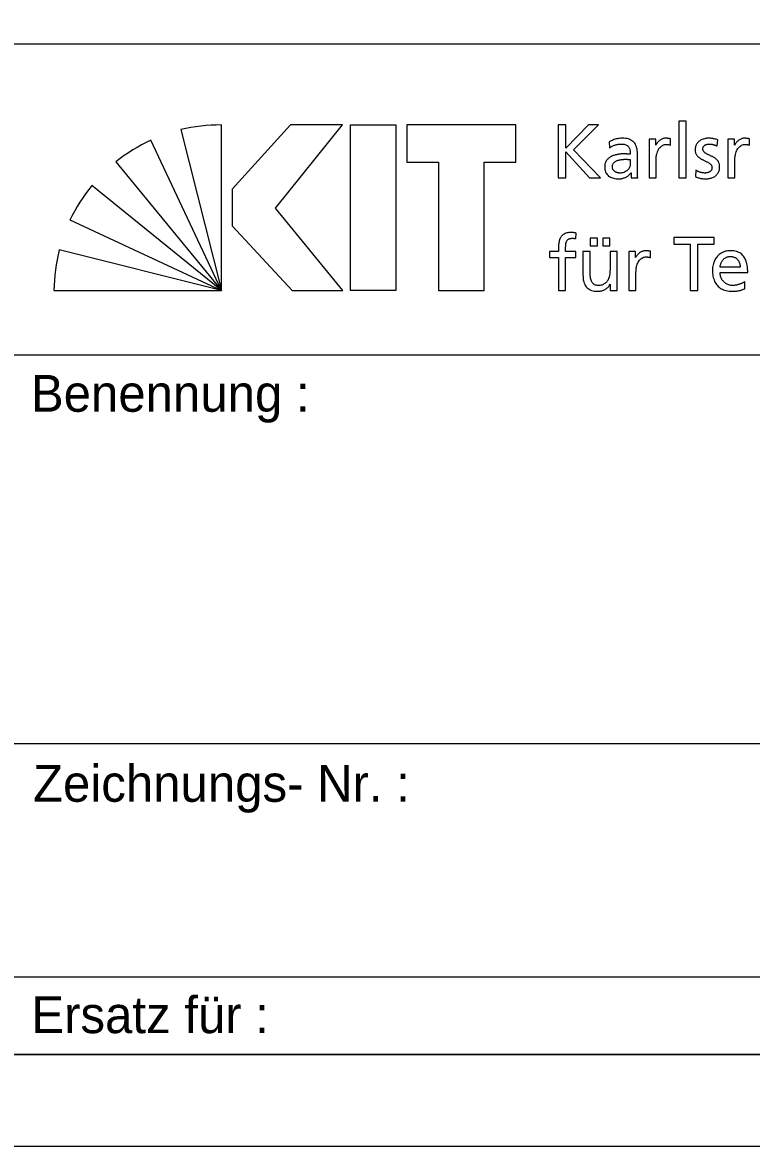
# Model space of a CAD drawing. Extents: x 0 to 75, y 0 to 42.1.
# Drawn here: x 70.583 to 72.566, y 0 to 3.058 of the extents above; entities that cross this region are included whole.
import ezdxf

# ---------------------------------------------------------------- set-up
doc = ezdxf.new("R2010")
doc.units = 0
doc.layers.add('90_Plankopf', color=7, linetype='Continuous')

msp = doc.modelspace()

# ---------------------------------------------------------------- linework, layer by layer
at = {"layer": '90_Plankopf'}
for p, q in [((65.856, 2.9995), (74.75, 2.9995)), ((65.856, 2.9995), (74.75, 2.9995)), ((71.0137, 2.7666), (71.124, 2.3293)), ((71.124, 2.3293), (71.124, 2.7792)), ((72.0405, 2.7793), (72.0405, 2.6353)), ((71.124, 2.3293), (70.9317, 2.7376)), ((72.179, 2.7331), (72.18, 2.7166)), ((72.3463, 2.7242), (72.3463, 2.7416)), ((72.4728, 2.722), (72.4745, 2.7389)), ((72.5606, 2.7242), (72.5606, 2.7416)), ((72.2559, 2.6559), (72.2559, 2.6995)), ((70.8372, 2.6793), (71.124, 2.3293)), ((72.2365, 2.6854), (72.2365, 2.6761)), ((72.0405, 2.6353), (72.0611, 2.6353)), ((72.1253, 2.6353), (72.1554, 2.6353)), ((72.4149, 2.6559), (72.4138, 2.6386)), ((71.124, 2.3293), (70.7717, 2.6143)), ((70.712, 2.5207), (71.124, 2.3293)), ((72.0887, 2.4696), (72.0895, 2.4853)), ((71.124, 2.3293), (70.6829, 2.4394)), ((72.2913, 2.4182), (72.2913, 2.4356)), ((72.5353, 2.392), (72.4808, 2.392)), ((72.4808, 2.3776), (72.5559, 2.3776)), ((70.6682, 2.3293), (71.124, 2.3293)), ((72.5479, 2.3337), (72.5479, 2.353)), ((70.55, 2.1535), (74.75, 2.1535)), ((70.55, 1.096), (74.75, 1.096)), ((70.55, 0.4615), (74.75, 0.4615)), ((74.75, 0.25), (65.856, 0.25)), ((66.44, 0.25), (74.75, 0.25)), ((66.44, 0.25), (74.75, 0.25))]:
    msp.add_line(p, q, dxfattribs=at)
for points in [[(0, 42.05), (75, 42.05), (75, 0), (0, 0)], [(71.4533, 2.7793), (71.3118, 2.7793), (71.1536, 2.6049), (71.1536, 2.5046), (71.3169, 2.3293), (71.4542, 2.3293), (71.2711, 2.5531)], [(71.5985, 2.7793), (71.5985, 2.3293), (71.4751, 2.3293), (71.4751, 2.7793)], [(71.6281, 2.7793), (71.6281, 2.678), (71.7151, 2.678), (71.7151, 2.3293), (71.8385, 2.3293), (71.8385, 2.678), (71.9255, 2.678), (71.9255, 2.7793)]]:
    msp.add_lwpolyline(points, close=True, dxfattribs=at)
for points in [[(59.6038, 0.25), (74.75, 0.25), (74.75, 41.8), (59.6038, 41.8)], [(72.369, 2.6353), (72.3884, 2.6353), (72.3884, 2.79), (72.369, 2.79), (72.369, 2.6353)], [(72.1554, 2.6353), (72.0824, 2.7112), (72.15, 2.7793), (72.1226, 2.7793), (72.0611, 2.716), (72.0611, 2.7793), (72.0405, 2.7793)], [(72.3061, 2.7242), (72.3057, 2.7242), (72.3057, 2.7405), (72.2875, 2.7405), (72.2875, 2.6353), (72.3069, 2.6353), (72.3069, 2.6832)], [(72.5203, 2.7242), (72.5199, 2.7242), (72.5199, 2.7405), (72.5018, 2.7405), (72.5018, 2.6353), (72.5212, 2.6353), (72.5212, 2.6832)], [(72.0611, 2.6353), (72.0611, 2.7059), (72.1253, 2.6353)], [(72.2382, 2.6489), (72.2386, 2.6489), (72.2386, 2.6353), (72.2567, 2.6353)], [(72.1277, 2.4713), (72.1277, 2.4506), (72.1471, 2.4506), (72.1471, 2.4713), (72.1277, 2.4713)], [(72.1615, 2.4713), (72.1615, 2.4506), (72.1809, 2.4506), (72.1809, 2.4713), (72.1615, 2.4713)], [(72.3995, 2.3293), (72.4201, 2.3293), (72.4201, 2.4552), (72.4649, 2.4552), (72.4649, 2.4733), (72.3547, 2.4733), (72.3547, 2.4552), (72.3995, 2.4552), (72.3995, 2.3293)], [(72.0412, 2.4443), (72.0412, 2.4346), (72.0165, 2.4346), (72.0165, 2.4189), (72.0412, 2.4189), (72.0412, 2.3293), (72.0606, 2.3293), (72.0606, 2.4189), (72.0885, 2.4189), (72.0885, 2.4346), (72.0606, 2.4346), (72.0606, 2.4459)], [(72.1271, 2.3801), (72.1271, 2.4346), (72.1077, 2.4346), (72.1077, 2.372)], [(72.2007, 2.3293), (72.2007, 2.4346), (72.1813, 2.4346), (72.1813, 2.3859)], [(72.2511, 2.4182), (72.2507, 2.4182), (72.2507, 2.4346), (72.2325, 2.4346), (72.2325, 2.3293), (72.2519, 2.3293), (72.2519, 2.3772)], [(72.1816, 2.346), (72.182, 2.346), (72.182, 2.3293), (72.2007, 2.3293)]]:
    msp.add_lwpolyline(points, dxfattribs=at)
for centre, start, end in [((71.1224, 2.3028), 89.8053, 103.1895), ((71.1331, 2.3059), 115.0126, 128.3968), ((71.1408, 2.3131), 140.7898, 154.174), ((71.1446, 2.3219), 165.7222, 179.1064)]:
    msp.add_arc(centre, 0.4764, start, end, dxfattribs=at)
for points in [[(72.2559, 2.6995), (72.256, 2.709), (72.2545, 2.717), (72.2517, 2.7235), (72.2488, 2.73), (72.2442, 2.7348), (72.238, 2.7381), (72.2317, 2.7413), (72.2236, 2.743), (72.2136, 2.743), (72.2069, 2.743), (72.2007, 2.742), (72.1949, 2.7402), (72.1891, 2.7384), (72.1838, 2.7361), (72.179, 2.7331)], [(72.18, 2.7166), (72.1826, 2.7188), (72.1856, 2.7207), (72.189, 2.7223), (72.1923, 2.7239), (72.1958, 2.7251), (72.1995, 2.726), (72.2032, 2.7269), (72.2068, 2.7273), (72.2105, 2.7273), (72.217, 2.7273), (72.2221, 2.7263), (72.2259, 2.7243), (72.2297, 2.7222), (72.2324, 2.7191), (72.2341, 2.7151), (72.2358, 2.711), (72.2365, 2.7059), (72.2365, 2.6999)], [(72.3463, 2.7416), (72.345, 2.7418), (72.3437, 2.7421), (72.3425, 2.7423), (72.3412, 2.7425), (72.3399, 2.7427), (72.3385, 2.7428), (72.3371, 2.7429), (72.3354, 2.743), (72.3335, 2.743), (72.3298, 2.743), (72.3261, 2.7422), (72.3226, 2.7406), (72.3191, 2.739), (72.3159, 2.7368), (72.313, 2.7339), (72.3101, 2.7311), (72.3078, 2.7279), (72.3061, 2.7242)], [(72.3069, 2.6832), (72.3069, 2.692), (72.3081, 2.6996), (72.3105, 2.706), (72.3129, 2.7124), (72.3162, 2.7174), (72.3205, 2.7208), (72.3247, 2.7243), (72.3298, 2.726), (72.3356, 2.7261), (72.3373, 2.7261), (72.339, 2.726), (72.3409, 2.7257), (72.3427, 2.7254), (72.3445, 2.7249), (72.3463, 2.7242)], [(72.4745, 2.7389), (72.4707, 2.74), (72.4669, 2.741), (72.463, 2.7418), (72.4591, 2.7426), (72.4549, 2.743), (72.4504, 2.743), (72.4451, 2.743), (72.4403, 2.7423), (72.4358, 2.741), (72.4313, 2.7397), (72.4274, 2.7377), (72.424, 2.735), (72.4206, 2.7323), (72.418, 2.729), (72.4161, 2.7249), (72.4142, 2.7208), (72.4132, 2.7161), (72.4132, 2.7106), (72.4132, 2.7064), (72.4141, 2.7028), (72.4158, 2.6997), (72.4174, 2.6966), (72.4195, 2.694), (72.4223, 2.6917), (72.425, 2.6895), (72.4279, 2.6875), (72.4312, 2.6857), (72.4344, 2.684), (72.4376, 2.6824), (72.4409, 2.6809), (72.4441, 2.6793), (72.4471, 2.6777), (72.4498, 2.6761), (72.4525, 2.6745), (72.4547, 2.6727), (72.4563, 2.6706), (72.4579, 2.6686), (72.4588, 2.6663), (72.4588, 2.6636), (72.4588, 2.6607), (72.4582, 2.6584), (72.457, 2.6564), (72.4558, 2.6545), (72.4542, 2.6529), (72.4522, 2.6518), (72.4503, 2.6506), (72.4482, 2.6498), (72.4459, 2.6493), (72.4435, 2.6487), (72.4412, 2.6485), (72.439, 2.6485), (72.4371, 2.6485), (72.4347, 2.6488), (72.432, 2.6493), (72.4292, 2.6499), (72.4263, 2.6507), (72.4233, 2.6518), (72.4203, 2.6529), (72.4175, 2.6543), (72.4149, 2.6559)], [(72.4138, 2.6386), (72.4183, 2.6363), (72.423, 2.6347), (72.4279, 2.6339), (72.4328, 2.6331), (72.4377, 2.6327), (72.4427, 2.6328), (72.4475, 2.6328), (72.452, 2.6335), (72.4564, 2.6348), (72.4607, 2.6361), (72.4647, 2.6381), (72.4681, 2.6408), (72.4716, 2.6435), (72.4743, 2.6469), (72.4764, 2.651), (72.4784, 2.6551), (72.4794, 2.66), (72.4795, 2.6656), (72.4794, 2.6704), (72.4786, 2.6745), (72.4769, 2.6778), (72.4753, 2.6811), (72.4731, 2.684), (72.4704, 2.6863), (72.4677, 2.6886), (72.4647, 2.6906), (72.4615, 2.6922), (72.4583, 2.6939), (72.455, 2.6954), (72.4518, 2.6968), (72.4486, 2.6983), (72.4456, 2.6998), (72.4429, 2.7013), (72.4402, 2.7029), (72.438, 2.7047), (72.4364, 2.7068), (72.4347, 2.7089), (72.4339, 2.7115), (72.4338, 2.7145), (72.4339, 2.7174), (72.4348, 2.7198), (72.4365, 2.7217), (72.4382, 2.7236), (72.4404, 2.725), (72.4432, 2.7259), (72.446, 2.7269), (72.4491, 2.7273), (72.4524, 2.7273), (72.4536, 2.7273), (72.4551, 2.7271), (72.4569, 2.7269), (72.4588, 2.7266), (72.4607, 2.7261), (72.4627, 2.7256), (72.4648, 2.7251), (72.4667, 2.7246), (72.4685, 2.7239), (72.4703, 2.7233), (72.4717, 2.7226), (72.4728, 2.722)], [(72.5606, 2.7416), (72.5592, 2.7418), (72.5579, 2.7421), (72.5567, 2.7423), (72.5555, 2.7425), (72.5541, 2.7427), (72.5527, 2.7428), (72.5513, 2.7429), (72.5497, 2.743), (72.5478, 2.743), (72.544, 2.743), (72.5404, 2.7422), (72.5368, 2.7406), (72.5333, 2.739), (72.5301, 2.7368), (72.5273, 2.7339), (72.5244, 2.7311), (72.5221, 2.7279), (72.5203, 2.7242)], [(72.5212, 2.6832), (72.5212, 2.692), (72.5224, 2.6996), (72.5247, 2.706), (72.5271, 2.7124), (72.5304, 2.7174), (72.5347, 2.7208), (72.539, 2.7243), (72.544, 2.726), (72.5498, 2.7261), (72.5515, 2.7261), (72.5533, 2.726), (72.5551, 2.7257), (72.557, 2.7254), (72.5588, 2.7249), (72.5606, 2.7242)], [(72.2365, 2.6999), (72.234, 2.7), (72.2317, 2.7001), (72.2295, 2.7001), (72.2273, 2.7002), (72.2251, 2.7003), (72.2229, 2.7003), (72.2208, 2.7003), (72.2184, 2.7003), (72.2159, 2.7003), (72.2118, 2.7003), (72.2076, 2.6999), (72.2031, 2.6992), (72.1987, 2.6985), (72.1943, 2.6973), (72.19, 2.6957), (72.1858, 2.6941), (72.1819, 2.6919), (72.1784, 2.6892), (72.175, 2.6866), (72.1722, 2.6833), (72.1701, 2.6794), (72.1681, 2.6755), (72.1671, 2.6709), (72.167, 2.6656), (72.1671, 2.658), (72.1687, 2.6518), (72.1719, 2.6469), (72.1752, 2.6421), (72.1797, 2.6385), (72.1855, 2.6362), (72.1913, 2.6339), (72.1979, 2.6328), (72.2056, 2.6328), (72.21, 2.6328), (72.214, 2.6334), (72.2175, 2.6344), (72.221, 2.6355), (72.2241, 2.6368), (72.2268, 2.6384), (72.2295, 2.6401), (72.2318, 2.6419), (72.2337, 2.6437), (72.2355, 2.6455), (72.237, 2.6472), (72.2382, 2.6489)], [(72.2365, 2.6761), (72.2365, 2.6709), (72.2354, 2.6661), (72.2332, 2.662), (72.231, 2.6578), (72.2277, 2.6546), (72.2233, 2.6522), (72.219, 2.6498), (72.2136, 2.6485), (72.2072, 2.6485), (72.205, 2.6485), (72.2027, 2.6489), (72.2004, 2.6496), (72.1981, 2.6503), (72.196, 2.6514), (72.1941, 2.6529), (72.1922, 2.6543), (72.1906, 2.6561), (72.1894, 2.6582), (72.1883, 2.6604), (72.1877, 2.6628), (72.1876, 2.6656), (72.1877, 2.6693), (72.1886, 2.6724), (72.1904, 2.6749), (72.1922, 2.6773), (72.1946, 2.6793), (72.1975, 2.6807), (72.2003, 2.6822), (72.2034, 2.6833), (72.2067, 2.6841), (72.21, 2.6848), (72.2132, 2.6853), (72.2163, 2.6855), (72.2194, 2.6858), (72.222, 2.6859), (72.2241, 2.6858), (72.2262, 2.6858), (72.2283, 2.6858), (72.2303, 2.6856), (72.2324, 2.6855), (72.2345, 2.6855), (72.2365, 2.6854)], [(72.2567, 2.6353), (72.2566, 2.6363), (72.2565, 2.6377), (72.2563, 2.6393), (72.2562, 2.6411), (72.2561, 2.6433), (72.2561, 2.646), (72.256, 2.6486), (72.2559, 2.652), (72.2559, 2.6559)], [(72.0895, 2.4853), (72.0875, 2.4856), (72.0855, 2.4859), (72.0834, 2.4862), (72.0812, 2.4864), (72.079, 2.4866), (72.0765, 2.4866), (72.0694, 2.4865), (72.0635, 2.4855), (72.0589, 2.4836), (72.0543, 2.4816), (72.0507, 2.4787), (72.0481, 2.475), (72.0455, 2.4713), (72.0437, 2.4668), (72.0427, 2.4616), (72.0417, 2.4565), (72.0412, 2.4507), (72.0412, 2.4443)], [(72.0606, 2.4459), (72.0606, 2.4495), (72.0608, 2.4528), (72.0612, 2.4558), (72.0616, 2.4588), (72.0625, 2.4615), (72.0637, 2.4637), (72.065, 2.466), (72.0669, 2.4677), (72.0694, 2.469), (72.0719, 2.4702), (72.0752, 2.4709), (72.0794, 2.4709), (72.0811, 2.4709), (72.0828, 2.4708), (72.0844, 2.4706), (72.0861, 2.4703), (72.0875, 2.47), (72.0887, 2.4696)], [(72.2913, 2.4356), (72.29, 2.4359), (72.2887, 2.4361), (72.2875, 2.4363), (72.2863, 2.4365), (72.2849, 2.4367), (72.2835, 2.4368), (72.2821, 2.437), (72.2804, 2.437), (72.2786, 2.437), (72.2748, 2.437), (72.2712, 2.4362), (72.2676, 2.4346), (72.2641, 2.433), (72.2609, 2.4308), (72.2581, 2.428), (72.2552, 2.4252), (72.2529, 2.4219), (72.2511, 2.4182)], [(72.2519, 2.3772), (72.252, 2.386), (72.2532, 2.3937), (72.2555, 2.4001), (72.2579, 2.4065), (72.2612, 2.4114), (72.2655, 2.4148), (72.2698, 2.4183), (72.2748, 2.4201), (72.2806, 2.4201), (72.2823, 2.4201), (72.2841, 2.42), (72.2859, 2.4197), (72.2878, 2.4195), (72.2896, 2.419), (72.2913, 2.4182)], [(72.5559, 2.3776), (72.556, 2.3861), (72.5552, 2.394), (72.5536, 2.4012), (72.552, 2.4084), (72.5495, 2.4146), (72.5459, 2.42), (72.5423, 2.4254), (72.5375, 2.4295), (72.5315, 2.4325), (72.5256, 2.4355), (72.5182, 2.437), (72.5095, 2.437), (72.502, 2.437), (72.4953, 2.4357), (72.4892, 2.4331), (72.4832, 2.4305), (72.478, 2.4269), (72.4737, 2.4221), (72.4694, 2.4174), (72.466, 2.4118), (72.4637, 2.4052), (72.4614, 2.3988), (72.4602, 2.3916), (72.4602, 2.3838), (72.4602, 2.3752), (72.4613, 2.3674), (72.4634, 2.3604), (72.4656, 2.3535), (72.469, 2.3475), (72.4734, 2.3425), (72.4779, 2.3375), (72.4835, 2.3336), (72.4904, 2.3309), (72.4973, 2.3282), (72.5053, 2.3269), (72.5147, 2.3268), (72.5204, 2.3269), (72.5253, 2.3273), (72.5293, 2.328), (72.5334, 2.3288), (72.5369, 2.3297), (72.5398, 2.3307), (72.5428, 2.3317), (72.5454, 2.3327), (72.5479, 2.3337)], [(72.4808, 2.392), (72.4812, 2.3955), (72.482, 2.3989), (72.4832, 2.4024), (72.4844, 2.4058), (72.4861, 2.4089), (72.4884, 2.4118), (72.4906, 2.4147), (72.4934, 2.417), (72.4969, 2.4187), (72.5003, 2.4204), (72.5043, 2.4213), (72.5091, 2.4213), (72.5133, 2.4213), (72.517, 2.4206), (72.5202, 2.419), (72.5235, 2.4175), (72.5262, 2.4154), (72.5285, 2.4127), (72.5307, 2.4101), (72.5324, 2.4069), (72.5335, 2.4034), (72.5347, 2.3999), (72.5353, 2.3961), (72.5353, 2.392)], [(72.1813, 2.3859), (72.1813, 2.3794), (72.1807, 2.3736), (72.1795, 2.3683), (72.1782, 2.363), (72.1763, 2.3584), (72.1736, 2.3546), (72.171, 2.3507), (72.1677, 2.3478), (72.1637, 2.3457), (72.1596, 2.3436), (72.1549, 2.3426), (72.1494, 2.3425), (72.1438, 2.3429), (72.1393, 2.3444), (72.1361, 2.3473), (72.1328, 2.3501), (72.1305, 2.3542), (72.1291, 2.3597), (72.1277, 2.3651), (72.1271, 2.3719), (72.1271, 2.3801)], [(72.1077, 2.372), (72.1077, 2.3626), (72.1091, 2.3545), (72.1118, 2.3478), (72.1146, 2.341), (72.119, 2.3359), (72.1248, 2.3323), (72.1306, 2.3287), (72.138, 2.3269), (72.1471, 2.3268), (72.152, 2.3269), (72.1568, 2.3276), (72.1613, 2.3291), (72.1658, 2.3307), (72.1698, 2.3329), (72.1733, 2.3357), (72.1768, 2.3386), (72.1796, 2.342), (72.1816, 2.346)], [(72.5479, 2.353), (72.5467, 2.3521), (72.5449, 2.351), (72.5426, 2.3497), (72.5403, 2.3485), (72.5377, 2.3474), (72.5347, 2.3463), (72.5317, 2.3452), (72.5286, 2.3443), (72.5253, 2.3436), (72.522, 2.3429), (72.5187, 2.3426), (72.5155, 2.3425), (72.5108, 2.3426), (72.5065, 2.3434), (72.5023, 2.3451), (72.4982, 2.3468), (72.4945, 2.3492), (72.4913, 2.3523), (72.488, 2.3554), (72.4855, 2.359), (72.4836, 2.3633), (72.4818, 2.3676), (72.4809, 2.3724), (72.4808, 2.3776)]]:
    msp.add_open_spline(points, degree=3, dxfattribs=at)

# ---------------------------------------------------------------- texts
for s, p in [('Benennung :', (70.6057, 1.999)), ('Zeichnungs- Nr. :', (70.6114, 0.9379)), ('Ersatz für :', (70.6069, 0.3084))]:
    msp.add_text(s, height=0.1, dxfattribs=at).set_placement(p)

doc.saveas('drawing.dxf')
